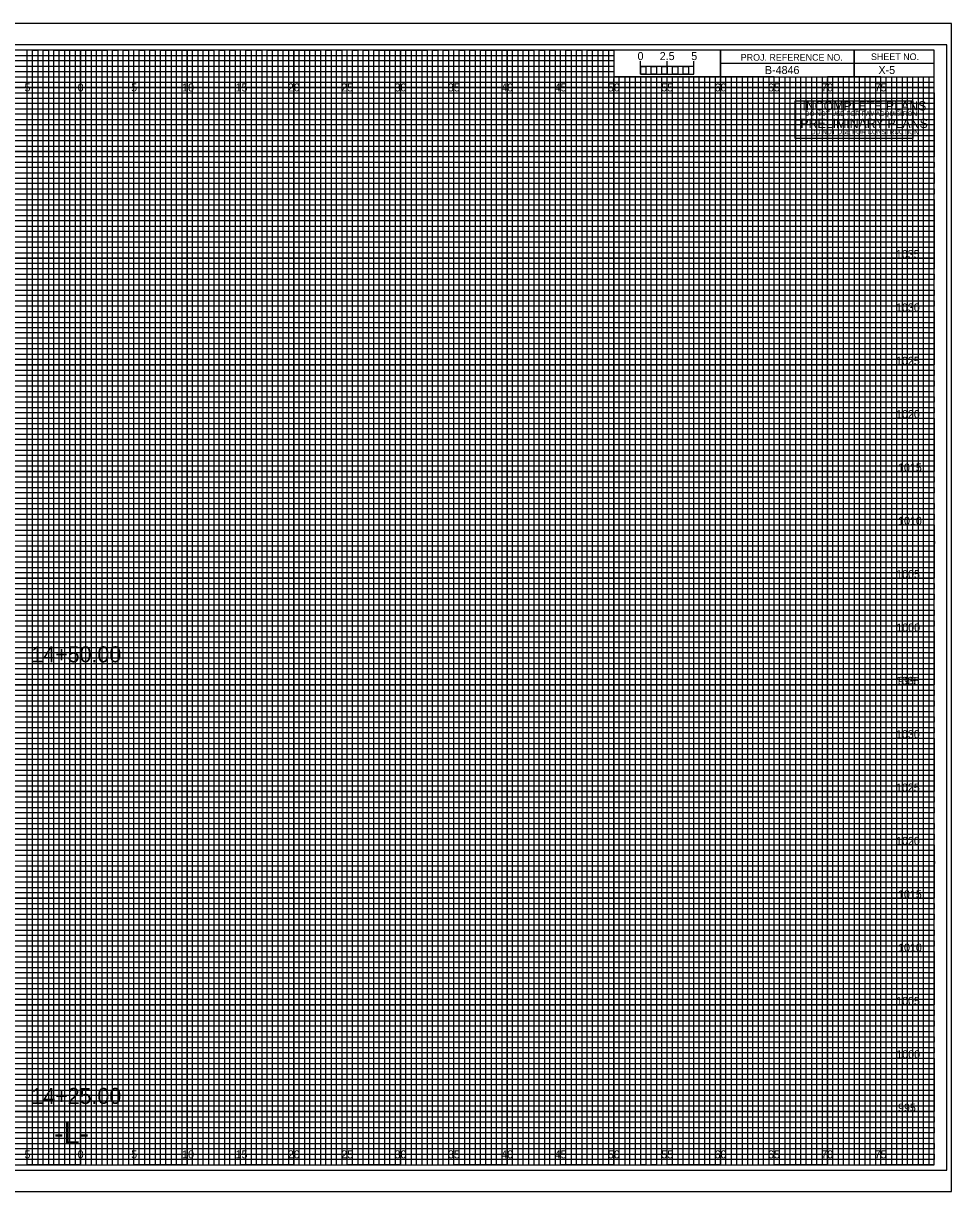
# Model space of a CAD drawing. Extents: x -7 to 162, y -2 to 987.
# Drawn here: x 74.6 to 161.7, y 437.5 to 547 of the extents above; entities that cross this region are included whole.
import ezdxf

# ---------------------------------------------------------------- set-up
doc = ezdxf.new("R2010")
doc.units = 0
for name, color, linetype in [('Default', 7, 'Continuous'), ('Exist Cross Section Cell', 7, 'Continuous'), ('Exist XS Center Line Elevation Label', 7, 'Continuous'), ('Exist XS Ground Line', 7, 'Continuous'), ('Prop CMT Concrete Structures', 7, 'Continuous'), ('Prop CMT DNC', 7, 'Continuous'), ('Prop CMT Guardrail Graphics', 7, 'Continuous'), ('Prop CMT Guardrail Widen Shoulder', 7, 'Continuous'), ('Prop CMT Pvmt Course 1', 7, 'Continuous'), ('Prop CMT Pvmt Surface', 7, 'Continuous'), ('Prop CMT Pvmt Surface Shoulder', 7, 'Continuous'), ('Prop CMT Shld Paved Course 1', 7, 'Continuous'), ('Prop CMT Shoulder Point', 7, 'Continuous'), ('Prop CMT Slope Grass', 7, 'Continuous'), ('Prop CMT Subgrade Earthwork', 7, 'Continuous'), ('Prop XS SE Text', 7, 'Continuous'), ('Prop XS Side Slope Text', 7, 'Continuous'), ('Typical Text Label CELL', 7, 'Continuous')]:
    doc.layers.add(name, color=color, linetype=linetype)

msp = doc.modelspace()

# ---------------------------------------------------------------- linework, layer by layer
at = {"layer": 'Default'}
for points in [[(146.99, 537.97), (146.99, 539.73), (158.01, 539.73), (158.01, 537.97)], [(146.99, 536.2), (146.99, 537.97), (158.01, 537.97), (158.01, 536.2)]]:
    msp.add_lwpolyline(points, close=True, dxfattribs=at)
at = {"layer": 'Exist XS Center Line Elevation Label'}
for points in [[(72.5, 440), (77.5, 440), (77.5, 544.5), (82.5, 544.5), (82.5, 440), (87.5, 440), (87.5, 544.5), (92.5, 544.5), (92.5, 440), (97.5, 440), (97.5, 544.5), (102.5, 544.5), (102.5, 440), (107.5, 440), (107.5, 544.5), (112.5, 544.5), (112.5, 440), (117.5, 440), (117.5, 544.5), (122.5, 544.5), (122.5, 440), (127.5, 440), (127.5, 544.5), (129.97, 544.5), (130, 544.5), (130, 542), (132.5, 542), (132.5, 440), (137.5, 440), (137.5, 542), (142.5, 542), (142.5, 440), (147.5, 440), (147.5, 542), (152.5, 542), (152.5, 440), (157.5, 440), (157.5, 542)], [(0, 542), (137.5, 542)], [(0, 532.5), (160, 532.5), (160, 537.5), (0, 537.5)], [(0, 522.5), (160, 522.5), (160, 527.5), (0, 527.5)], [(0, 512.5), (160, 512.5), (160, 517.5), (0, 517.5)], [(0, 502.5), (160, 502.5), (160, 507.5), (0, 507.5)], [(0, 492.5), (160, 492.5), (160, 497.5), (0, 497.5)], [(0, 482.5), (160, 482.5), (160, 487.5), (0, 487.5)], [(0, 472.5), (160, 472.5), (160, 477.5), (0, 477.5)], [(0, 462.5), (160, 462.5), (160, 467.5), (0, 467.5)], [(0, 452.5), (160, 452.5), (160, 457.5), (0, 457.5)], [(0, 442.5), (160, 442.5), (160, 447.5), (0, 447.5)]]:
    msp.add_lwpolyline(points, dxfattribs=at)
at = {"layer": 'Exist XS Ground Line'}
for p, q in [((75, 544.5), (70, 544.5)), ((75, 440), (75, 544.5)), ((85, 544.5), (80, 544.5)), ((80, 544.5), (80, 440)), ((85, 440), (85, 544.5)), ((95, 544.5), (90, 544.5)), ((90, 544.5), (90, 440)), ((95, 440), (95, 544.5)), ((105, 544.5), (100, 544.5)), ((100, 544.5), (100, 440)), ((105, 440), (105, 544.5)), ((115, 544.5), (110, 544.5)), ((110, 544.5), (110, 440)), ((115, 440), (115, 544.5)), ((125, 544.5), (120, 544.5)), ((120, 544.5), (120, 440)), ((125, 440), (125, 544.5)), ((130, 544.5), (130, 440)), ((135, 440), (135, 542)), ((145, 542), (140, 542)), ((140, 542), (140, 440)), ((145, 440), (145, 542)), ((155, 542), (150, 542)), ((150, 542), (150, 440)), ((155, 440), (155, 542)), ((80, 440), (75, 440)), ((90, 440), (85, 440)), ((100, 440), (95, 440)), ((110, 440), (105, 440)), ((120, 440), (115, 440)), ((130, 440), (125, 440)), ((140, 440), (135, 440)), ((150, 440), (145, 440)), ((160, 440), (155, 440)), ((160, 440), (160, 440))]:
    msp.add_line(p, q, dxfattribs=at)
for points in [[(0, 540), (160, 540), (160, 535), (0, 535)], [(0, 530), (160, 530), (160, 525), (0, 525)], [(0, 520), (160, 520), (160, 515), (0, 515)], [(0, 510), (160, 510), (160, 505), (0, 505)], [(0, 500), (160, 500), (160, 495), (0, 495)], [(0, 490), (160, 490), (160, 485), (0, 485)], [(0, 480), (160, 480), (160, 475), (0, 475)], [(0, 470), (160, 470), (160, 465), (0, 465)], [(0, 460), (160, 460), (160, 455), (0, 455)], [(0, 450), (160, 450), (160, 445), (0, 445)]]:
    msp.add_lwpolyline(points, dxfattribs=at)
at = {"layer": 'Prop CMT Concrete Structures'}
for p, q in [((75, 440), (75, 544.5)), ((80, 440), (80, 544.5)), ((85, 440), (85, 544.5)), ((90, 440), (90, 544.5)), ((95, 440), (95, 544.5)), ((100, 440), (100, 544.5)), ((105, 440), (105, 544.5)), ((110, 440), (110, 544.5)), ((115, 440), (115, 544.5)), ((120, 440), (120, 544.5)), ((125, 440), (125, 544.5)), ((130, 440), (130, 541.84)), ((135, 440), (135, 541.84)), ((140, 440), (140, 541.84)), ((145, 440), (145, 541.84)), ((150, 440), (150, 541.84)), ((155, 440), (155, 541.84)), ((0, 540), (160, 540)), ((0, 535), (160, 535)), ((0, 530), (160, 530)), ((0, 525), (160, 525)), ((0, 520), (160, 520)), ((0, 515), (160, 515)), ((0, 510), (160, 510)), ((0, 505), (160, 505)), ((0, 500), (160, 500)), ((0, 495), (160, 495)), ((0, 490), (160, 490)), ((0, 485), (160, 485)), ((0, 480), (160, 480)), ((0, 475), (160, 475)), ((0, 470), (160, 470)), ((0, 465), (160, 465)), ((0, 460), (160, 460)), ((0, 455), (160, 455)), ((0, 450), (160, 450)), ((0, 445), (160, 445))]:
    msp.add_line(p, q, dxfattribs=at)
at = {"layer": 'Prop CMT Guardrail Widen Shoulder'}
for p, q in [((161.65, 547), (-6.7, 547)), ((-6.7, 437.5), (161.65, 437.5))]:
    msp.add_line(p, q, dxfattribs=at)
at = {"layer": 'Prop CMT Pvmt Course 1'}
msp.add_lwpolyline([(-6.7, 437.5), (161.65, 437.5), (161.65, 547), (-6.7, 547)], close=True, dxfattribs=at)
at = {"layer": 'Prop CMT Pvmt Surface'}
for p, q in [((133.5, 542), (133, 542)), ((133, 542), (133, 440)), ((133.5, 440), (133.5, 542)), ((134.5, 542), (134, 542)), ((134, 542), (134, 440)), ((134.5, 440), (134.5, 542)), ((133, 440), (132.5, 440)), ((134, 440), (133.5, 440))]:
    msp.add_line(p, q, dxfattribs=at)
for points in [[(75, 440), (75.5, 440), (75.5, 544.5), (76, 544.5), (76, 440)], [(76, 440), (76.5, 440), (76.5, 544.5), (77, 544.5), (77, 440)], [(77.5, 440), (78, 440), (78, 544.5), (78.5, 544.5), (78.5, 440)], [(78.5, 440), (79, 440), (79, 544.5), (79.5, 544.5), (79.5, 440)], [(80, 440), (80.5, 440), (80.5, 544.5), (81, 544.5), (81, 440)], [(81, 440), (81.5, 440), (81.5, 544.5), (82, 544.5), (82, 440)], [(82.5, 440), (83, 440), (83, 544.5), (83.5, 544.5), (83.5, 440)], [(83.5, 440), (84, 440), (84, 544.5), (84.5, 544.5), (84.5, 440)], [(85, 440), (85.5, 440), (85.5, 544.5), (86, 544.5), (86, 440)], [(86, 440), (86.5, 440), (86.5, 544.5), (87, 544.5), (87, 440)], [(87.5, 440), (88, 440), (88, 544.5), (88.5, 544.5), (88.5, 440)], [(88.5, 440), (89, 440), (89, 544.5), (89.5, 544.5), (89.5, 440)], [(90, 440), (90.5, 440), (90.5, 544.5), (91, 544.5), (91, 440)], [(91, 440), (91.5, 440), (91.5, 544.5), (92, 544.5), (92, 440)], [(92.5, 440), (93, 440), (93, 544.5), (93.5, 544.5), (93.5, 440)], [(93.5, 440), (94, 440), (94, 544.5), (94.5, 544.5), (94.5, 440)], [(95, 440), (95.5, 440), (95.5, 544.5), (96, 544.5), (96, 440)], [(96, 440), (96.5, 440), (96.5, 544.5), (97, 544.5), (97, 440)], [(97.5, 440), (98, 440), (98, 544.5), (98.5, 544.5), (98.5, 440)], [(98.5, 440), (99, 440), (99, 544.5), (99.5, 544.5), (99.5, 440)], [(100, 440), (100.5, 440), (100.5, 544.5), (101, 544.5), (101, 440)], [(101, 440), (101.5, 440), (101.5, 544.5), (102, 544.5), (102, 440)], [(102.5, 440), (103, 440), (103, 544.5), (103.5, 544.5), (103.5, 440)], [(103.5, 440), (104, 440), (104, 544.5), (104.5, 544.5), (104.5, 440)], [(105, 440), (105.5, 440), (105.5, 544.5), (106, 544.5), (106, 440)], [(106, 440), (106.5, 440), (106.5, 544.5), (107, 544.5), (107, 440)], [(107.5, 440), (108, 440), (108, 544.5), (108.5, 544.5), (108.5, 440)], [(108.5, 440), (109, 440), (109, 544.5), (109.5, 544.5), (109.5, 440)], [(110, 440), (110.5, 440), (110.5, 544.5), (111, 544.5), (111, 440)], [(111, 440), (111.5, 440), (111.5, 544.5), (112, 544.5), (112, 440)], [(112.5, 440), (113, 440), (113, 544.5), (113.5, 544.5), (113.5, 440)], [(113.5, 440), (114, 440), (114, 544.5), (114.5, 544.5), (114.5, 440)], [(115, 440), (115.5, 440), (115.5, 544.5), (116, 544.5), (116, 440)], [(116, 440), (116.5, 440), (116.5, 544.5), (117, 544.5), (117, 440)], [(117.5, 440), (118, 440), (118, 544.5), (118.5, 544.5), (118.5, 440)], [(118.5, 440), (119, 440), (119, 544.5), (119.5, 544.5), (119.5, 440)], [(120, 440), (120.5, 440), (120.5, 544.5), (121, 544.5), (121, 440)], [(121, 440), (121.5, 440), (121.5, 544.5), (122, 544.5), (122, 440)], [(122.5, 440), (123, 440), (123, 544.5), (123.5, 544.5), (123.5, 440)], [(123.5, 440), (124, 440), (124, 544.5), (124.5, 544.5), (124.5, 440)], [(125, 440), (125.5, 440), (125.5, 544.5), (126, 544.5), (126, 440)], [(126, 440), (126.5, 440), (126.5, 544.5), (127, 544.5), (127, 440)], [(127.5, 440), (128, 440), (128, 544.5), (128.5, 544.5), (128.5, 440)], [(128.5, 440), (129, 440), (129, 544.5), (129.5, 544.5), (129.5, 440)], [(130, 440), (130.5, 440), (130.5, 542), (131.01, 542), (131.01, 440)], [(131, 440), (131.5, 440), (131.5, 542), (132, 542), (132, 440)], [(135, 440), (135.49, 440), (135.49, 542), (136, 542), (136, 440)], [(136, 440), (136.5, 440), (136.5, 542), (137.03, 542), (137.03, 440)], [(137.5, 440), (138, 440), (138, 542), (138.5, 542), (138.5, 440)], [(138.5, 440), (139, 440), (139, 542), (139.5, 542), (139.5, 440)], [(140, 440), (140.5, 440), (140.5, 542), (141, 542), (141, 440)], [(141, 440), (141.5, 440), (141.5, 542), (142, 542), (142, 440)], [(142.5, 440), (143, 440), (143, 542), (143.5, 542), (143.5, 440)], [(143.5, 440), (144, 440), (144, 542), (144.5, 542), (144.5, 440)], [(145, 440), (145.5, 440), (145.5, 542), (146, 542), (146, 440)], [(146, 440), (146.5, 440), (146.5, 542), (147, 542), (147, 440)], [(147.5, 440), (148, 440), (148, 542), (148.5, 542), (148.5, 440)], [(148.5, 440), (149, 440), (149, 542), (149.5, 542), (149.5, 440)], [(150, 440), (150.5, 440), (150.5, 542), (151, 542), (151, 440)], [(151, 440), (151.5, 440), (151.5, 542), (152, 542), (152, 440)], [(152.5, 440), (153, 440), (153, 542), (153.5, 542), (153.5, 440)], [(153.5, 440), (154, 440), (154, 542), (154.5, 542), (154.5, 440)], [(155, 440), (155.5, 440), (155.5, 542), (156, 542), (156, 440)], [(156, 440), (156.5, 440), (156.5, 542), (157, 542), (157, 440)], [(157.5, 440), (158, 440), (158, 542), (158.5, 542), (158.5, 440)], [(158.5, 440), (159, 440), (159, 542), (159.5, 542), (159.5, 440)]]:
    msp.add_lwpolyline(points, dxfattribs=at)
at = {"layer": 'Prop CMT Pvmt Surface Shoulder'}
for p, q in [((132.5, 542.25), (132.5, 543.45)), ((132.5, 542.95), (132.5, 543.45)), ((135, 542.25), (135, 543.45)), ((137.5, 542.25), (137.5, 543.45)), ((137.5, 542.95), (137.5, 543.45))]:
    msp.add_line(p, q, dxfattribs=at)
for points in [[(137.5, 542.95), (132.5, 542.95), (132.5, 542.25), (137.5, 542.25)], [(132.5, 542.95), (133, 542.95), (133, 542.25), (132.5, 542.25)], [(133.5, 542.95), (134, 542.95), (134, 542.25), (133.5, 542.25)], [(134.5, 542.95), (135, 542.95), (135, 542.25), (134.5, 542.25)], [(135.5, 542.95), (136, 542.95), (136, 542.25), (135.5, 542.25)], [(136.5, 542.95), (137, 542.95), (137, 542.25), (136.5, 542.25)]]:
    msp.add_lwpolyline(points, close=True, dxfattribs=at)
at = {"layer": 'Prop CMT Shld Paved Course 1'}
for p, q in [((0, 544), (130, 544)), ((130, 543.49), (0, 543.49)), ((130, 544), (130, 543.49)), ((0, 543), (130, 543)), ((130, 542.45), (0, 542.45)), ((130, 543), (130, 542.45)), ((0, 541.5), (160, 541.5))]:
    msp.add_line(p, q, dxfattribs=at)
for points in [[(0, 541), (135, 541), (160, 541), (160, 541), (0, 541)], [(0, 540.5), (160, 540.5), (160, 539.5), (0, 539.5)], [(0, 539), (160, 539), (160, 538.5), (0, 538.49)], [(0, 538), (160, 538), (160, 537), (0, 537)], [(0, 536.5), (160, 536.5), (160, 536), (0, 536)], [(0, 535.5), (160, 535.5), (160, 534.5), (0, 534.5)], [(0, 534), (160, 534), (160, 533.5), (0, 533.5)], [(0, 533), (160, 533), (160, 532), (0, 532)], [(0, 531.5), (160, 531.5), (160, 531), (0, 531)], [(0, 530.5), (160, 530.5), (160, 529.5), (0, 529.5)], [(0, 529), (160, 529), (160, 528.5), (0, 528.5)], [(0, 528), (160, 528), (160, 526.98), (160, 526.5), (160, 526), (0, 526)], [(0, 527), (160, 527), (160, 526.5), (0, 526.5)], [(0, 525.5), (160, 525.5), (160, 524.5), (0, 524.51)], [(0, 524.51), (160, 524.5), (160, 524), (0, 524)], [(0, 523.5), (160, 523.5), (160, 523), (0, 523)], [(0, 522), (160, 522), (160, 521.5), (0, 521.5)], [(0, 521), (160, 521), (160, 520.5), (0, 520.5)], [(-0.04, 519.45), (160, 519.45), (160, 518.94), (-0.04, 518.94)], [(0, 518.5), (160, 518.5), (160, 518), (0, 518)], [(0, 517), (160, 517), (160, 516.5), (0, 516.5)], [(0, 516), (160, 516), (160, 515.5), (0, 515.5)], [(0, 514.5), (160, 514.5), (160, 514), (0, 514)], [(0, 513.5), (160, 513.5), (160, 513), (0, 513)], [(0, 512), (160, 512), (160, 511.5), (0, 511.5)], [(0, 511), (160, 511), (160, 510.5), (0, 510.5)], [(0, 509.5), (160, 509.5), (160, 508.99), (0, 509)], [(0, 508.5), (160, 508.5), (160, 508), (0, 508)], [(0, 507), (160, 507), (160, 506.5), (0, 506.5)], [(0, 506), (160, 506), (160, 505.5), (0, 505.5)], [(0, 504.5), (160, 504.5), (160, 504), (0, 504)], [(0, 503.5), (160, 503.5), (160, 503), (0, 503)], [(0, 502), (160, 502), (160, 501.5), (0, 501.5)], [(0, 501), (160, 501), (160, 500.5), (0, 500.5)], [(0, 499.5), (160, 499.5), (160, 499), (0, 499)], [(0, 498.5), (160.03, 498.45), (160, 498), (0, 498)], [(0, 497), (160, 497), (160, 496.5), (0, 496.5)], [(0, 496), (160, 496), (160, 495.5), (0, 495.5)], [(0, 494.5), (160, 494.5), (160, 494), (0, 494)], [(0, 493.5), (160, 493.5), (160, 493), (0, 493)], [(0, 492), (160, 492), (160, 491.5), (0, 491.5)], [(0, 491), (160, 491), (160, 490.5), (0, 490.5)], [(0, 489.5), (160, 489.5), (160, 489), (0, 489)], [(0, 488.5), (160, 488.5), (160, 488), (0, 488)], [(0, 487), (160, 487), (160, 486.5), (0, 486.5)], [(0, 486), (160, 486), (160, 485.5), (0, 485.5)], [(0, 484.5), (160, 484.5), (160, 484), (0, 484)], [(0, 483.5), (160, 483.5), (160, 483), (0, 483)], [(0, 482), (160, 482), (160, 481.5), (0, 481.5)], [(0, 481), (160, 481), (160, 480.5), (0, 480.5)], [(0, 479.5), (160, 479.5), (160, 478.99), (0, 479)], [(0, 478.5), (160, 478.5), (160, 478), (0, 478)], [(0, 477), (160, 477), (160, 476.5), (0, 476.5)], [(0, 476), (160, 476), (160, 475.5), (0, 475.5)], [(0, 474.5), (160, 474.5), (160, 474), (0, 474)], [(0, 473.5), (160, 473.5), (160, 473), (0, 473)], [(0, 472), (160, 472), (160, 471.5), (0, 471.5)], [(0, 471), (160, 471), (160, 470.5), (0, 470.5)], [(0, 469.5), (160, 469.5), (160, 469), (0, 469)], [(0, 468.5), (160.03, 468.45), (160, 468), (0, 468)], [(0, 467), (160, 467), (160, 466.5), (0, 466.5)], [(0, 466), (160, 466), (160, 465.5), (0, 465.5)], [(0, 464.5), (160, 464.5), (160, 464), (0, 464)], [(0, 463.5), (160, 463.5), (160, 463), (0, 463)], [(0, 462), (160, 462), (160, 461.5), (0, 461.5)], [(0, 461), (160, 461), (160, 460.5), (0, 460.5)], [(0, 459.5), (160, 459.5), (160, 459), (0, 459)], [(0, 458.5), (160, 458.5), (160, 458), (0, 458)], [(0, 457), (160, 457), (160, 456.5), (0, 456.5)], [(0, 456), (160, 456), (160, 455.5), (0, 455.5)], [(0, 454.5), (160, 454.5), (160, 454), (0, 454)], [(0, 453.5), (160, 453.5), (160, 453), (0, 453)], [(0, 452), (160, 452), (160, 451.5), (0, 451.5)], [(0, 451), (160, 451), (160, 450.5), (0, 450.5)], [(0, 449.5), (160, 449.5), (160, 449), (0, 449)], [(0, 448.5), (160, 448.5), (160, 448), (0, 448)], [(0, 447), (160, 447), (160, 446.5), (0, 446.5)], [(0, 446), (160, 446), (160, 445.5), (0, 445.5)], [(0, 444.5), (160, 444.5), (160, 444), (0, 444)], [(0, 443.5), (160, 443.5), (160, 443), (0, 443)], [(0, 442), (160, 442), (160, 441.5), (0, 441.5)], [(0, 441), (160, 441), (160, 440.5), (0, 440.5)]]:
    msp.add_lwpolyline(points, dxfattribs=at)
at = {"layer": 'Prop CMT Slope Grass'}
msp.add_lwpolyline([(-5.4, 439.5), (161.2, 439.5), (161.2, 545), (-5.4, 545)], close=True, dxfattribs=at)
at = {"layer": 'Prop CMT Subgrade Earthwork'}
for p, q in [((152.5, 544.5), (152.5, 542)), ((152.5, 542), (152.5, 544.5)), ((160, 543.25), (140, 543.25)), ((140, 543.25), (140, 542)), ((140, 542), (160, 542))]:
    msp.add_line(p, q, dxfattribs=at)
for points in [[(160, 544.5), (0, 544.5), (0, 440), (160, 440)], [(140, 544.5), (130, 544.5), (130, 542.01), (140, 542.01)], [(160, 544.5), (140, 544.5), (140, 542), (160, 542)]]:
    msp.add_lwpolyline(points, close=True, dxfattribs=at)

# ---------------------------------------------------------------- texts
at = {"layer": 'Default'}
for s, height, p in [('INCOMPLETE PLANS', 0.864, (147.66, 538.84)), ('DO NOT USE FOR R/W ACQUISITION', 0.432, (147.9, 538.32)), ('PRELIMINARY PLANS', 0.864, (147.47, 537.19)), ('DO NOT USE FOR CONSTRUCTION', 0.432, (148.46, 536.61))]:
    msp.add_text(s, height=height, dxfattribs=at).set_placement(p)
at = {"layer": 'Exist Cross Section Cell'}
for s, p in [('5', (74.74, 540.62)), ('0', (79.73, 540.62)), ('0', (79.73, 540.62)), ('5', (84.74, 540.62)), ('10', (89.52, 540.62)), ('15', (94.53, 540.62)), ('20', (99.43, 540.62)), ('25', (104.44, 540.62)), ('30', (109.43, 540.62)), ('35', (114.44, 540.62)), ('40', (119.43, 540.62)), ('45', (124.44, 540.62)), ('50', (129.43, 540.62)), ('55', (134.44, 540.62)), ('60', (139.43, 540.62)), ('65', (144.44, 540.62)), ('70', (149.43, 540.62)), ('75', (154.44, 540.62)), ('5', (74.74, 440.62)), ('0', (79.73, 440.62)), ('0', (79.73, 440.62)), ('5', (84.74, 440.62)), ('10', (89.52, 440.62)), ('15', (94.53, 440.62)), ('20', (99.43, 440.62)), ('25', (104.44, 440.62)), ('30', (109.43, 440.62)), ('35', (114.44, 440.62)), ('40', (119.43, 440.62)), ('45', (124.44, 440.62)), ('50', (129.43, 440.62)), ('55', (134.44, 440.62)), ('60', (139.43, 440.62)), ('65', (144.44, 440.62)), ('70', (149.43, 440.62)), ('75', (154.44, 440.62))]:
    msp.add_text(s, height=0.75, dxfattribs=at).set_placement(p)
at = {"layer": 'Prop CMT DNC'}
msp.add_text('-L-', height=2, dxfattribs=at).set_placement((77.53, 442))
at = {"layer": 'Prop CMT Guardrail Graphics'}
msp.add_text('B-4846', height=0.75, dxfattribs=at).set_placement((144.15, 542.25))
at = {"layer": 'Prop CMT Pvmt Surface Shoulder'}
msp.add_text('0', height=0.75, dxfattribs=at).set_placement((132.21, 543.56))
at = {"layer": 'Prop CMT Shoulder Point'}
for s, p in [('2.5', (134.29, 543.56)), ('5', (137.24, 543.56))]:
    msp.add_text(s, height=0.75, dxfattribs=at).set_placement(p)
at = {"layer": 'Prop CMT Subgrade Earthwork'}
for s, p in [('PROJ. REFERENCE NO.', (141.88, 543.5)), ('SHEET NO.', (154.09, 543.56))]:
    msp.add_text(s, height=0.625, dxfattribs=at).set_placement(p)
at = {"layer": 'Prop XS SE Text'}
msp.add_text('X-5', height=0.75, dxfattribs=at).set_placement((154.79, 542.25))
at = {"layer": 'Prop XS Side Slope Text'}
for s, p in [('14+50.00', (75.39, 487.11)), ('14+25.00', (75.39, 445.72))]:
    msp.add_text(s, height=1.5, dxfattribs=at).set_placement(p)
at = {"layer": 'Typical Text Label CELL'}
for s, p in [('1035', (156.42, 525)), ('1030', (156.43, 520)), ('1025', (156.43, 515)), ('1020', (156.44, 510)), ('1015', (156.62, 505)), ('1010', (156.63, 500)), ('1005', (156.45, 495)), ('1000', (156.46, 490)), ('1035', (156.42, 485)), ('995', (156.62, 485)), ('1030', (156.43, 480)), ('1025', (156.43, 475)), ('1020', (156.44, 470)), ('1015', (156.62, 465)), ('1010', (156.63, 460)), ('1005', (156.45, 455)), ('1000', (156.46, 450)), ('995', (156.62, 445))]:
    msp.add_text(s, height=0.75, dxfattribs=at).set_placement(p)

doc.saveas('drawing.dxf')
